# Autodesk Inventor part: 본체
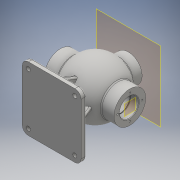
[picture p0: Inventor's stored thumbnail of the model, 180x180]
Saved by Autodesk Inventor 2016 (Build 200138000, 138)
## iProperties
Created: 2017-01
Part Number: 본체
Material: 일반
Document SubType Name: Modeling
Designer: Administrator
Density: 1 g/cm^3
Appearance: 기본값
Author: Administrator
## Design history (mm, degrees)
sketch "스케치1"
  geometry: L1 (57.5, 62.5)-(-57.5, 62.5); L2 (-57.5, 62.5)-(-57.5, -62.5); L3 (-57.5, -62.5)-(57.5, -62.5); L4 (57.5, -62.5)-(57.5, 62.5); 1 further point
  constraints: 8 end point, 2 parallel, 1 horizontal, 1 perpendicular
  dimensions: "d0" = 115 distance of L3.end L2.end; "d1" = 125 distance of L2.end L1.end; "d2" = 57.5 distance from line of point (0, 0) L4; "d3" = 62.5 distance from line of L1 point (0, 0)
extrude "돌출1" new body sketch "스케치1" stored distance "d4" = 10; taper "d5" = 0 deg
sketch "스케치2"
  geometry: 1 further point
sketch "스케치3"
  geometry: L1 (-5, -62.5)-(-5, 62.5) reference; L2 (-5, -62.5)-(5, -62.5) reference; L3 (49.016, -43)-(49.016, 43); L4 (80, 0)-(80, -53); L5 (80, 0)-(80, 53); A1 r 53 centre (80, 0) between (80, -53) and (80, 53); 1 further point
  constraints: 6 end point, 2 point on circle, 2 vertical, 1 centre point, 1 point on line
  dimensions: "d6" = 106 diameter of A1; "d7" = 85 distance from line of L4.start L1; "d8" = 62.5 distance from line of L4.start L2
revolve "회전1" sketch "스케치3" stored, may be unused: angle "d10" = 90 deg
sketch "스케치4"
  geometry: L1 (0, 80)-(-100.148, 80); L2 (-53, 80)-(-68, 80); L3 (-68, 80)-(-68, 111); L4 (-68, 111)-(-42.988, 111); A1 r 53 centre (0, 80) between (-53, 80) and (-42.988, 111) reference; 1 further point
  constraints: 8 end point, 2 perpendicular, 2 point on circle, 2 point on line, 1 horizontal
  dimensions: "d11" = 15 distance of L2.start L2.end; "d12" = 31 distance of L2.end L3.end
revolve "회전2" sketch "스케치4" stored, may be unused: angle "d13" = 90 deg
sketch "스케치5"
  geometry: L1 (-57.5, -5)-(57.5, -5) reference; L2 (57.5, -5)-(57.5, 5) reference; L3 (0, 80)-(-68, 80); L4 (-68, 49)-(-68, 111) reference; L5 (0, 80)-(68, 80); L6 (68, 49)-(68, 111) reference; L7 (-68, 80)-(-68, 97.5); L8 (-68, 97.5)-(-39.278, 97.5); L9 (68, 80)-(68, 97.5); L10 (68, 97.5)-(39.278, 97.5); A1 r 43 centre (0, 80) between (39.278, 97.5) and (-39.278, 97.5); 1 further point
  constraints: 12 end point, 2 midpoint, 2 point on circle, 2 point on line, 1 centre point, 1 horizontal, 1 perpendicular
  dimensions: "d14" = 86 diameter of A1; "d15" = 85 distance from line of L3.start L1; "d16" = 57.5 distance from line of L3.start L2; "d17" = 17.5 distance of L3.end L7.end
revolve "회전3" sketch "스케치5" stored, may be unused: angle "d18" = 90 deg
node "작업 평면1"
sketch "스케치6"
  geometry: C1 r 27 at (0, 0); 1 further point
  constraints: 1 centre point, 1 coincident
  dimensions: "d20" = 54 diameter of C1
extrude "돌출2" join sketch "스케치6" stored distance "d21" = 10; taper "d22" = 0 deg
sketch "스케치7"
  geometry: C1 r 13 at (0, 0); 1 further point
  constraints: 1 centre point, 1 coincident
  dimensions: "d23" = 26 diameter of C1
extrude "돌출3" cut sketch "스케치7" distance "d24" = 40; taper "d25" = 0 deg
fillet "모깎기1" dims "d26" = 12
fillet "모깎기2" dims "d27" = 12
sketch "스케치8"
  geometry: A1 r 12 centre (45.5, -50.5) between (45.5, -62.5) and (57.5, -50.5) reference; A2 r 12 centre (-45.5, -50.5) between (-57.5, -50.5) and (-45.5, -62.5) reference; A3 r 12 centre (45.5, 50.5) between (57.5, 50.5) and (45.5, 62.5) reference; A4 r 12 centre (-45.5, 50.5) between (-45.5, 62.5) and (-57.5, 50.5) reference; 5 further points
  constraints: 4 coincident
hole "구멍1" sketch "스케치8" at (45.5, -50.5), (-45.5, -50.5), (45.5, 50.5), (-45.5, 50.5) diameter "d28" = 8; stored, may be unused: countersink angle "d32" = 90 deg, drill point angle "d34" = 118 deg; dims "d29" = 6, "d30" = 12, "d31" = 3, "d33" = 8
fillet "모깎기3" dims "d35" = 3
sketch "스케치9"
  geometry: L1 (5, 50.5)-(5, -50.5) reference; L2 (5, 52.5)-(38.993, 38.766); L3 (5, 52.5)-(41.663, 52.5); L4 (5, -52.5)-(39.391, -38.605); L5 (5, -52.5)-(42.092, -52.5); L6 (5, 52.5)-(5, -52.5); L7 (2, -50.5)-(2, 50.5) reference; L8 (2, 62.5)-(-5, 62.5) reference; L9 (-5, -62.5)-(2, -62.5) reference; L10 (38.993, 38.766)-(42.426, 37.379); L11 (39.391, -38.605)-(42.426, -37.379); L12 (5, 52.5)-(5, -52.5); L13 (5, 56.5)-(5, 44.5) reference; A1 r 53 centre (80, 0) between (125.607, 27) and (125.607, -27) reference; 1 further point
  constraints: 16 end point, 3 point on line, 2 equal length, 2 horizontal, 2 point on circle, 1 collinear, 1 parallel
  dimensions: "d36" = 22 deg angle of L2 L3; "d37" = 22 deg angle of L5 L4; "d38" = 10 distance between parallel lines of L3 L8; "d39" = 10 distance from line of L9 L4.start
extrude "돌출4" join sketch "스케치9" stored distance "d40" = 8; taper "d41" = 0 deg
sketch "스케치10"
  geometry: 1 further point
sketch "스케치11"
  geometry: L1 (57.5, -5)-(57.5, 2) reference; L2 (57.5, 2)-(47.5, 2); L3 (45.5, 2)-(-45.5, 2) reference; L4 (47.5, 2)-(47.5, 5); L5 (47.5, 5)-(33.205, 40.382); L6 (47.5, 5)-(85.661, 5); 1 further point
  constraints: 9 end point, 1 collinear, 1 equal length, 1 horizontal, 1 perpendicular
  dimensions: "d42" = 10 distance of L1.end L2.end; "d43" = 112 deg angle of L6 L5
feature "리브1" sketch "스케치11" dims "d44" = 1, "d45" = 8, "d46" = 0, "d47" = 0, "d48" = 1, "d49" = 1
sketch "스케치12"
  geometry: A1 r 22.5 centre (0, 0) between (0, 22.5) and (-22.5, 0); 3 further points
  constraints: 4 point on circle, 1 centre point
  dimensions: "d50" = 45 diameter of A1
hole "구멍2" sketch "스케치12" at (0, 22.5), (-22.5, 0), (0, -22.5), (22.5, 0) diameter "d51" = 3.242; stored, may be unused: countersink angle "d55" = 90 deg, drill point angle "d57" = 118 deg; dims "d52" = 12, "d53" = 12, "d54" = 3, "d56" = 15
node "작업 평면2"
sketch "스케치14"
  geometry: L1 (0, -37.379)-(0, -4) reference; A1 r 20 centre (0, 0) between (-20, 0) and (0, -20); 3 further points
  constraints: 4 point on circle, 1 centre point, 1 coincident, 1 point on line
  dimensions: "d69" = 40 diameter of A1
hole "구멍4" sketch "스케치14" at (-20, 0), (0, 20), (20, 0), (0, -20) diameter "d70" = 3.242; stored, may be unused: countersink angle "d74" = 90 deg, drill point angle "d76" = 118 deg; dims "d71" = 9, "d72" = 12, "d73" = 3, "d75" = 11
sketch "스케치15"
  geometry: L1 (72.5, 150)-(18.5, 150) reference; L2 (18.5, 150)-(18.5, 130.607); L3 (18.5, 150)-(18.5, 130.607) reference; 2 further points
  constraints: 2 end point, 1 point on line, 1 other
  dimensions: "d77" = 10 distance from line of point (45.5, 140) L1; "d78" = 27 distance from line of point (45.5, 140) L2
sketch "스케치16"
  geometry: L1 (53, 80)-(68, 80); L2 (68, 80)-(68, 111); L3 (68, 111)-(42.988, 111); A1 r 53 centre (0, 80) between (33.719, 39.109) and (-33.719, 39.109) reference; 1 further point
  constraints: 6 end point, 2 point on circle, 1 horizontal, 1 perpendicular, 1 vertical
  dimensions: "d79" = 15 distance of L1.start L1.end; "d80" = 31 distance of L1.end L2.end
revolve "회전4" sketch "스케치16" stored, may be unused: angle "d81" = 90 deg
sketch "스케치17"
  geometry: L1 (68, 49)-(68, 111) reference; L2 (68, 97.5)-(52, 97.5); L3 (39.278, 97.5)-(50.027, 97.5) reference; L4 (68, 78.88)-(68, 97.5); L5 (68, 78.88)-(39.278, 78.88); L6 (39.278, 62.5)-(39.278, 97.5) reference; L7 (39.278, 78.88)-(39.278, 97.5); L8 (52, 97.5)-(52, 98.5); L9 (52, 98.5)-(50.25, 98.5); L10 (50.25, 98.5)-(50.25, 97.5); L11 (50.25, 97.5)-(39.278, 97.5); L12 (50.027, 97.5)-(50.027, 62.5) reference; 1 further point
  constraints: 16 end point, 4 perpendicular, 3 point on line, 2 collinear, 1 horizontal, 1 vertical
  dimensions: "d82" = 16 distance of L2.start L2.end; "d83" = 1 distance of L2.end L8.end; "d84" = 1.75 distance of L8.end L9.end; "d85" = 1 distance of L9.end L10.end
revolve "회전5" sketch "스케치17" stored, may be unused: angle "d86" = 90 deg
feature "엠보싱1" dims "d87" = 0.5, "d88" = 0
sketch "스케치18" dims "d89" = 48
  geometry: 3 further points
  constraints: 1 vertical alignment, 2 other
hole "구멍5" sketch "스케치18" at (0, 24) diameter "d90" = 3.242; stored, may be unused: countersink angle "d94" = 90 deg, drill point angle "d96" = 118 deg; dims "d91" = 16, "d92" = 12, "d93" = 3, "d95" = 19
fillet "모깎기4" dims "d100" = 3
fillet "모깎기5" dims "d101" = 3
fillet "모깎기6" dims "d102" = 3
chamfer "모따기1" distance "d103" = 1; stored, may be unused: second distance "d104" = 2, angle "d105" = 45 deg
fillet "모깎기7" dims "d106" = 3
chamfer "모따기2" distance "d107" = 1; stored, may be unused: second distance "d108" = 2, angle "d109" = 45 deg
node "솔리드1"
mirror "대칭2"
pattern_circular "원형 패턴2" dims angle "d98" = 360 deg
